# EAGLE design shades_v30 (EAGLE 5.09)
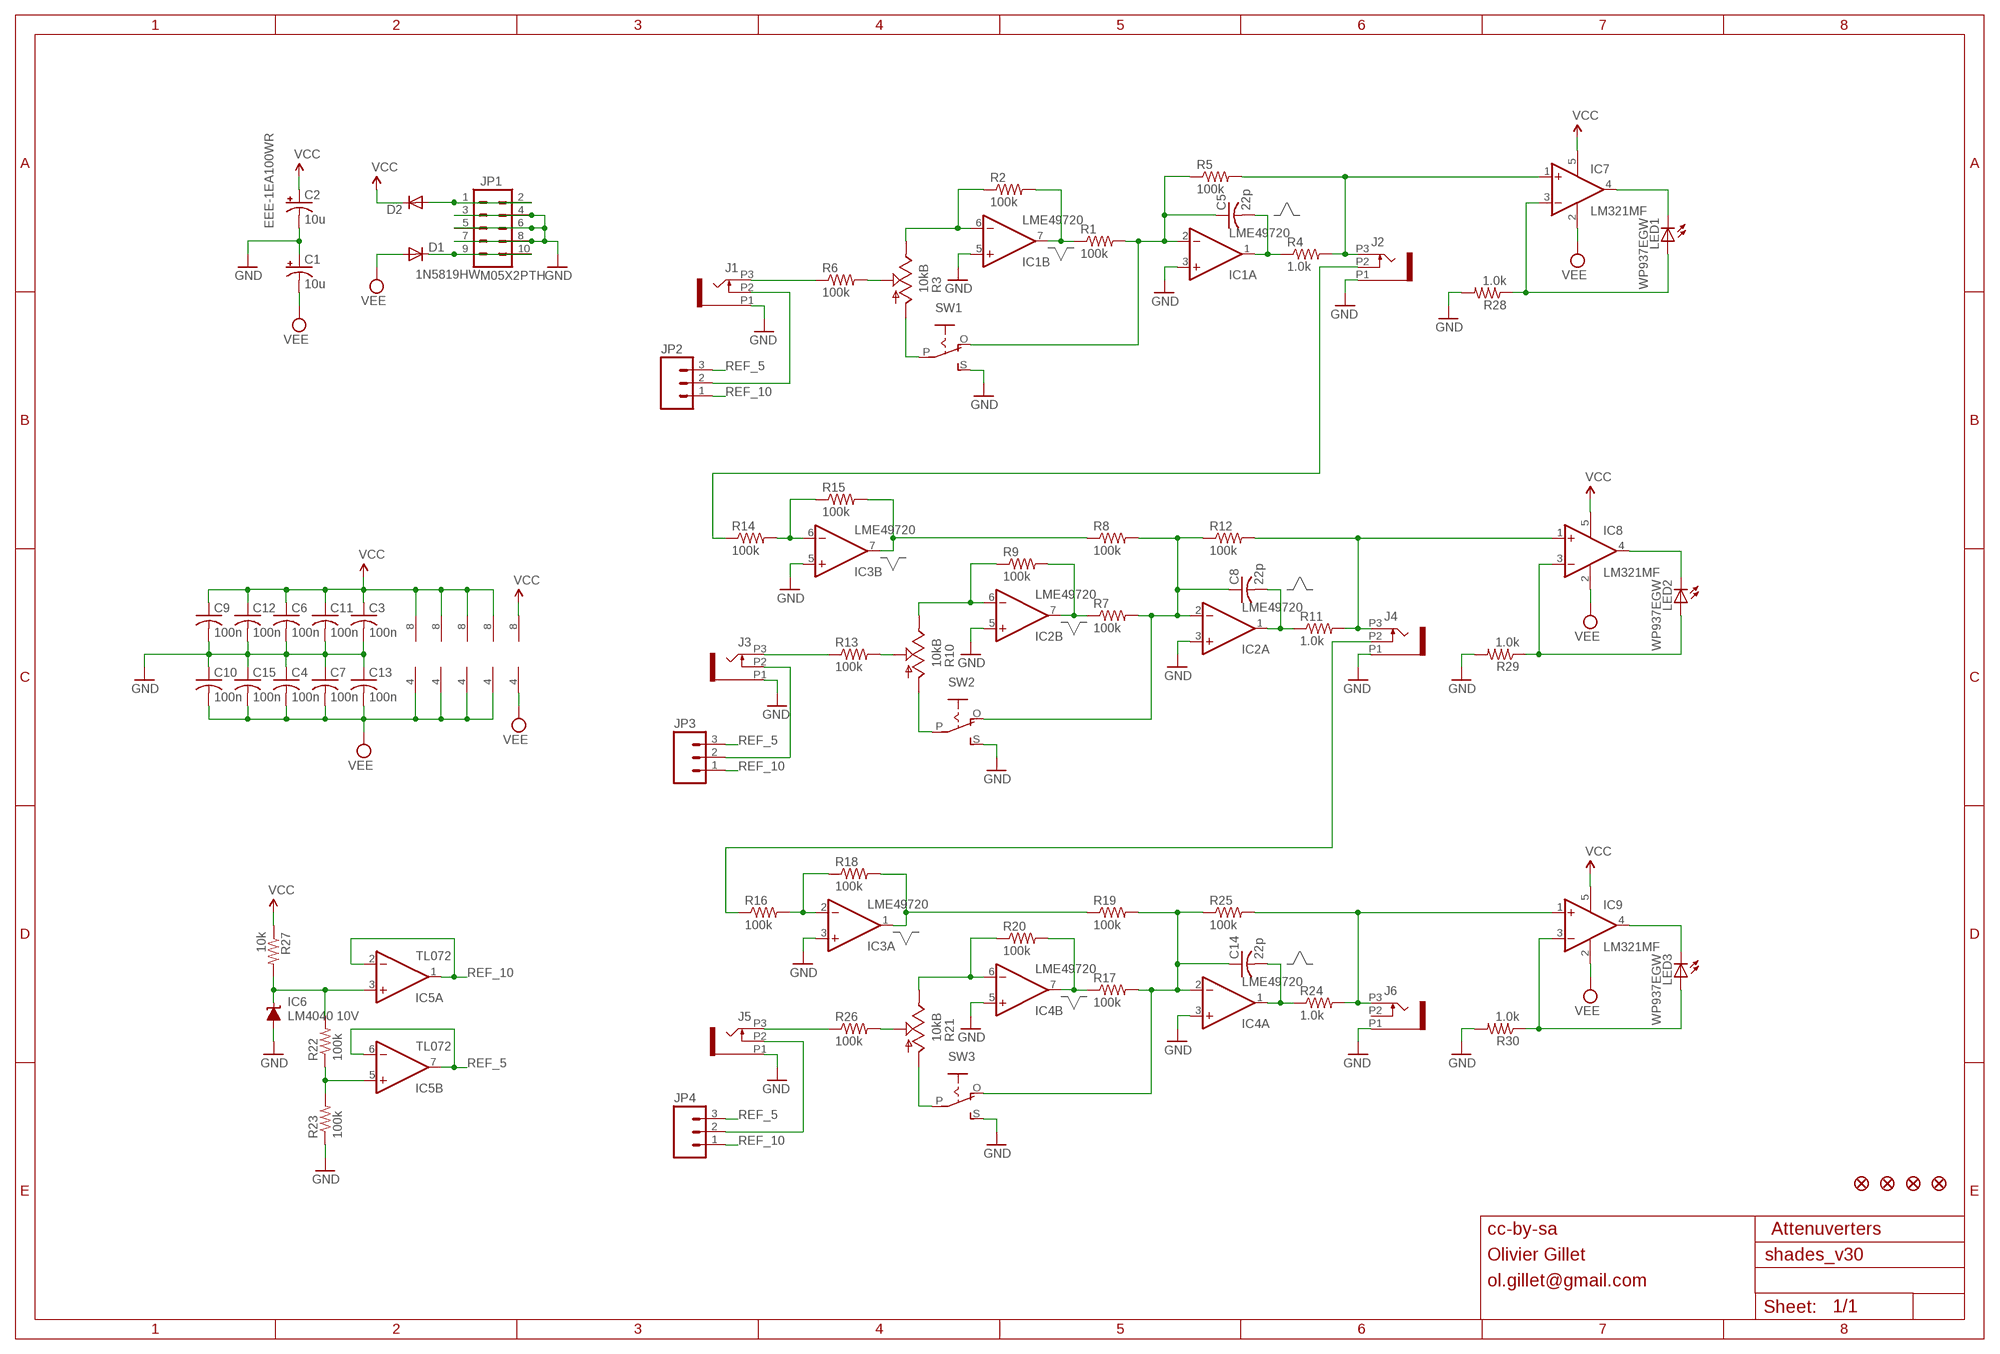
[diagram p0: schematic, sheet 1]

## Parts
C1  10u  CPOL-USB  [PANASONIC_B]
C2  10u  CPOL-USB  [PANASONIC_B]
C3  100n  C-USC0603  [C0603]
C4  100n  C-USC0603  [C0603]
C5  22p  C-USC0603  [C0603]
C6  100n  C-USC0603  [C0603]
C7  100n  C-USC0603  [C0603]
C8  22p  C-USC0603  [C0603]
C9  100n  C-USC0603  [C0603]
C10  100n  C-USC0603  [C0603]
C11  100n  C-USC0603  [C0603]
C12  100n  C-USC0603  [C0603]
C13  100n  C-USC0603  [C0603]
C14  22p  C-USC0603  [C0603]
C15  100n  C-USC0603  [C0603]
D1  1N5819HW  DIODE-SOD123  [SOD123]
D2  1N5819HW  DIODE-SOD123  [SOD123]
F1  FIDUCIAL1X2  [FIDUCIAL-1X2]
F2  FIDUCIAL1X2  [FIDUCIAL-1X2]
F3  FIDUCIAL1X2  [FIDUCIAL-1X2]
F4  FIDUCIAL1X2  [FIDUCIAL-1X2]
IC1  LME49720  TL072D  [SO08]
IC2  LME49720  TL072D  [SO08]
IC3  LME49720  TL072D  [SO08]
IC4  LME49720  TL072D  [SO08]
IC5  TL072  TL072D  [SO08]
IC6  LM4040 10V  LM4041C12DBZ  [DBZ_R-PDSO-G3]
IC7  LM321MF  [SOT23-5]
IC8  LM321MF  [SOT23-5]
IC9  LM321MF  [SOT23-5]
J1  PJ301_THONKICONN6  [WQP_PJ_301M6]
J2  PJ301_THONKICONN6  [WQP_PJ_301M6]
J3  PJ301_THONKICONN6  [WQP_PJ_301M6]
J4  PJ301_THONKICONN6  [WQP_PJ_301M6]
J5  PJ301_THONKICONN6  [WQP_PJ_301M6]
J6  PJ301_THONKICONN6  [WQP_PJ_301M6]
JP1  M05X2PTH  [AVR_ICSP]
JP2  M03PTH  [1X03]
JP3  M03PTH  [1X03]
JP4  M03PTH  [1X03]
LED1  WP937EGW  LED3MM  [LED3MM]
LED2  WP937EGW  LED3MM  [LED3MM]
LED3  WP937EGW  LED3MM  [LED3MM]
R1  100k  R-US_R0603  [R0603]
R2  100k  R-US_R0603  [R0603]
R3  10kB  POT_USVERTICAL_PS  [ALPS_POT_VERTICAL_PS]
R4  1.0k  R-US_R0603  [R0603]
R5  100k  R-US_R0603  [R0603]
R6  100k  R-US_R0603  [R0603]
R7  100k  R-US_R0603  [R0603]
R8  100k  R-US_R0603  [R0603]
R9  100k  R-US_R0603  [R0603]
R10  10kB  POT_USVERTICAL_PS  [ALPS_POT_VERTICAL_PS]
R11  1.0k  R-US_R0603  [R0603]
R12  100k  R-US_R0603  [R0603]
R13  100k  R-US_R0603  [R0603]
R14  100k  R-US_R0603  [R0603]
R15  100k  R-US_R0603  [R0603]
R16  100k  R-US_R0603  [R0603]
R17  100k  R-US_R0603  [R0603]
R18  100k  R-US_R0603  [R0603]
R19  100k  R-US_R0603  [R0603]
R20  100k  R-US_R0603  [R0603]
R21  10kB  POT_USVERTICAL_PS  [ALPS_POT_VERTICAL_PS]
R22  100k  R-US_R0603  [R0603]
R23  100k  R-US_R0603  [R0603]
R24  1.0k  R-US_R0603  [R0603]
R25  100k  R-US_R0603  [R0603]
R26  100k  R-US_R0603  [R0603]
R27  10k  R-US_R0603  [R0603]
R28  1.0k  R-US_R0603  [R0603]
R29  1.0k  R-US_R0603  [R0603]
R30  1.0k  R-US_R0603  [R0603]
SW1  S-ON-ONSMALL_SLIDE  [ES_100SP1T6B11M2QEH_SMALL]
SW2  S-ON-ONSMALL_SLIDE  [ES_100SP1T6B11M2QEH_SMALL]
SW3  S-ON-ONSMALL_SLIDE  [ES_100SP1T6B11M2QEH_SMALL]

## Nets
GND: C1.+ C2.- C3.2 C4.1 C6.2 C7.1 C9.2 C10.1 C11.2 C12.2 C13.1 C15.1 IC1.3(A:+IN) IC1.5(B:+IN) IC2.3(A:+IN) IC2.5(B:+IN) IC3.3(A:+IN) IC3.5(B:+IN) IC4.3(A:+IN) IC4.5(B:+IN) IC6.2(A) J1.P1 J2.P1 J3.P1 J4.P1 J5.P1 J6.P1 JP1.3 JP1.4 JP1.5 JP1.6 JP1.7 JP1.8 R23.1 R28.2 R29.2 R30.2 SW1.S SW2.S SW3.S
N$1: J1.P2 JP2.2
N$2: J3.P2 JP3.2
N$3: J5.P2 JP4.2
N$4: IC7.3(-IN) LED1.A R28.1
N$5: IC5.5(B:+IN) R22.1 R23.2
N$6: D2.A JP1.1 JP1.2
N$7: IC7.4(OUT) LED1.K(C)
N$9: J1.P3 R6.1
N$10: R3.P$2(S) R6.2
N$11: R3.P$3(A) SW1.P
N$12: C5.1 IC1.2(A:-IN) R1.2 R5.1 SW1.O
N$13: IC1.6(B:-IN) R2.1 R3.P$1(E)
N$14: IC1.7(B:OUT) R1.1 R2.2
N$15: C5.2 IC1.1(A:OUT) R4.1
N$16: J3.P3 R13.1
N$17: IC8.3(-IN) LED2.A R29.1
N$18: R10.P$2(S) R13.2
N$19: R10.P$3(A) SW2.P
N$20: D1.C JP1.9 JP1.10
N$22: IC2.6(B:-IN) R9.1 R10.P$1(E)
N$23: IC2.7(B:OUT) R7.1 R9.2
N$24: IC8.4(OUT) LED2.K(C)
N$25: C8.2 IC2.1(A:OUT) R11.1
N$26: J5.P3 R26.1
N$27: R21.P$2(S) R26.2
N$30: IC4.6(B:-IN) R20.1 R21.P$1(E)
N$31: IC4.7(B:OUT) R17.1 R20.2
N$33: C14.2 IC4.1(A:OUT) R24.1
N$34: IC9.3(-IN) LED3.A R30.1
N$35: IC9.4(OUT) LED3.K(C)
N$36: IC3.6(B:-IN) R14.2 R15.1
N$37: IC3.2(A:-IN) R16.2 R18.1
N$38: IC3.1(A:OUT) R18.2 R19.1
N$39: IC3.7(B:OUT) R8.1 R15.2
N$40: C14.1 IC4.2(A:-IN) R17.2 R19.2 R25.1 SW3.O
N$41: C8.1 IC2.2(A:-IN) R7.2 R8.2 R12.1 SW2.O
OUT_1: IC7.1(+IN) J2.P3 R4.2 R5.2
OUT_2: IC8.1(+IN) J4.P3 R11.2 R12.2
OUT_3: IC9.1(+IN) J6.P3 R24.2 R25.2
REF_5: IC5.6(B:-IN) IC5.7(B:OUT) JP2.3 JP3.3 JP4.3
REF_10: IC5.1(A:OUT) IC5.2(A:-IN) JP2.1 JP3.1 JP4.1
REF_10_UNBUF: IC5.3(A:+IN) IC6.1(C) R22.2 R27.2
SEND_1: J2.P2 R14.1
SEND_2: J4.P2 R16.1
SW3: R21.P$3(A) SW3.P
VCC: C2.+ C3.1 C6.1 C9.1 C11.1 C12.1 D2.C IC1.8(P:V+) IC2.8(P:V+) IC3.8(P:V+) IC4.8(P:V+) IC5.8(P:V+) IC7.5(V+) IC8.5(V+) IC9.5(V+) R27.1
VEE: C1.- C4.2 C7.2 C10.2 C13.2 C15.2 D1.A IC1.4(P:V-) IC2.4(P:V-) IC3.4(P:V-) IC4.4(P:V-) IC5.4(P:V-) IC7.2(V-) IC8.2(V-) IC9.2(V-)
Unconnected: J6.P2

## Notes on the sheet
- EEE-1EA100WR
- cc-by-sa | Attenuverters
- Olivier Gillet
- ol.gillet@gmail.com

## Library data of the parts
C1 C2 = rcl:CPOL-US: POLARIZED CAPACITOR, American symbol
C3-C15 = rcl:C-US: CAPACITOR, American symbol
D1 D2 = diode:DIODE-: DIODE
F1-F4 = SparkFun:FIDUCIAL: Fiducial Alignment Points
IC1-IC5 = gm-ics:TL072: OP AMP
IC6 = texas:LM4041: PRECISION MICROPOWER SHUNT VOLTAGE REFERENCE
IC7-IC9 = linear:LM321?*: Low Power Single Op Amp Source: http://cache.national.com/ds/LM/LM321.pdf
J1-J6 = og-pj301:PJ301_THONKICONN
JP1 = og-header:M05X2: Header 5x2 Standard 10-pin dual row 0.1" header. Commonly used with AVR-ISP. Use with Spark Fun Electronics SKU: PRT-00778
JP2-JP4 = SparkFun:M03: Header 3 Standard 3-pin 0.1" header. Use with straight break away headers (SKU : PRT-00116), right angle break away headers (PRT-00553), swiss pins (PRT-00743), machine pins (PRT-00117), and female headers (PRT-00115). Molex polarized connector foot print use with SKU : PRT-08232 with associated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
LED1-LED3 = led:LED: LED
R1 R2 R4-R9 R11-R20 R22-R26 R28-R30 = rcl:R-US_: RESISTOR, American symbol
R3 R10 R21 = pot-alps:POT_US
R27 = resistor:R-US_: RESISTOR, American symbol
SW1-SW3 = og-switch:S-ON-ON: On-on Switch

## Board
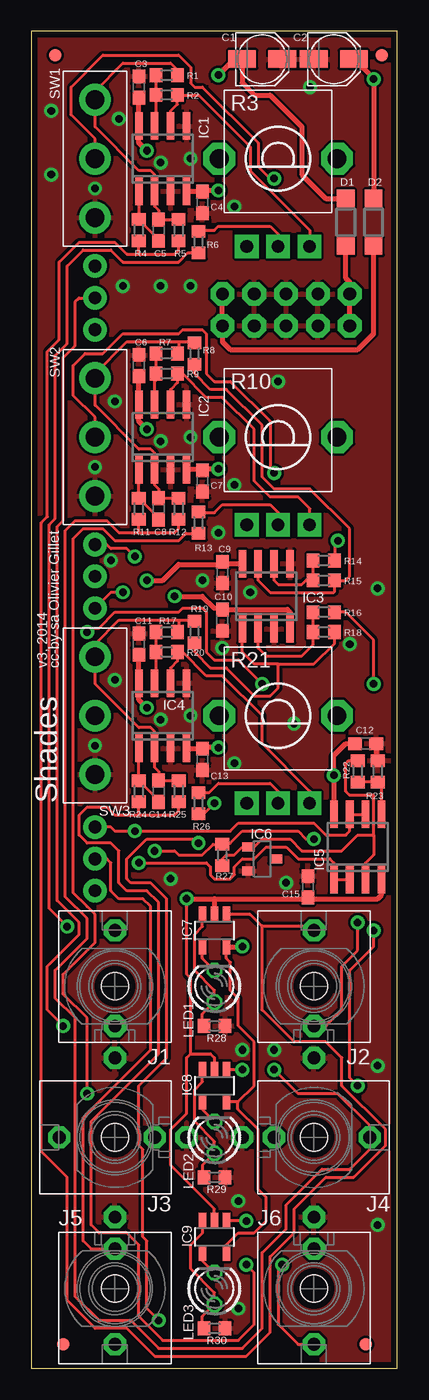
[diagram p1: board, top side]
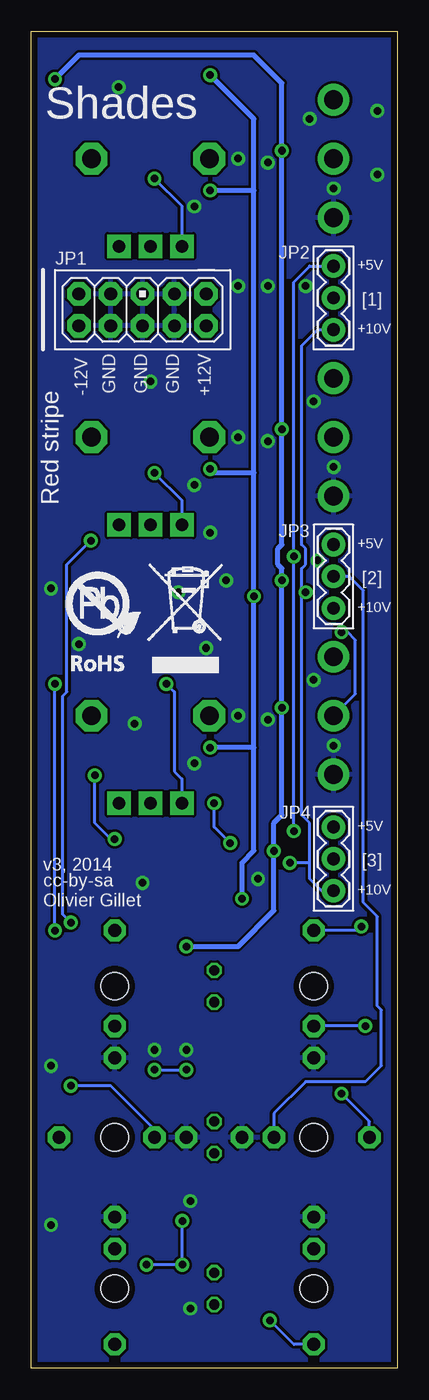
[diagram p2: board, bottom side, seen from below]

Size 29.19 x 106.68 mm. Coordinates in mm from the lower left corner, seen from the top.
Outline: 0,0 29.19,0 29.19,106.68 0,106.68 0,0
Copper layers (1*16): Top 0.035mm / dielectric 1.5mm / Bottom 0.035mm
Design rules "PCBCart-Standard": minimum track width 8mil, minimum drill 0.4mm, track to track 8mil, track to pad 8mil, pad to pad 8mil, via to via 8mil, smd to smd 8mil, copper to edge 20mil, drill to drill 8mil, minimum pad ring 8mil, minimum via ring 10mil, stop-mask expansion 3mil, vias tented up to drill 25mil, thermal gap 8mil

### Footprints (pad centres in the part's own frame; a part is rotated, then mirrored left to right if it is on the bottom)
PANASONIC_B = smd 2.2 x 1.4: + 1.6,0; - -1.6,0
C0603 = smd 1.1 x 1: 1 -0.85,0; 2 0.85,0
SOD123 = smd 1.4 x 1.4: A 1.9,0; C -1.9,0
FIDUCIAL-1X2 = smd 1 x 1: 1 0,0
SO08 = smd 0.6 x 2.2: 1 -1.905,-2.6; 2 -0.635,-2.6; 3 0.635,-2.6; 4 1.905,-2.6; 5 1.905,2.6; 6 0.635,2.6; 7 -0.635,2.6; 8 -1.905,2.6
DBZ_R-PDSO-G3 = smd 0.7 x 1: 1 -0.95,-1.1; 2 0.95,-1.1; 3 0,1.1
SOT23-5 = smd 0.6 x 1.2: 1 -0.95,-1.306; 2 0,-1.306; 3 0.95,-1.306; 4 0.95,1.306; 5 -0.95,1.306
WQP_PJ_301M6 = drill 1.016 pad 1.778 octagon: P1 0,-5.715; P2 0,-3.175; P3 0,4.445 | hole 2.2: 0,0
AVR_ICSP = drill 1.016 pad 1.88 octagon: 1 -1.27,5.08; 2 1.27,5.08; 3 -1.27,2.54; 4 1.27,2.54; 5 -1.27,0; 6 1.27,0; 7 -1.27,-2.54; 8 1.27,-2.54; 9 -1.27,-5.08; 10 1.27,-5.08
1X03 = drill 1.016 pad 1.88 round: 1 0,0; 2 2.54,0; 3 5.08,0
LED3MM = drill 0.813 octagon: A -1.27,0; K 1.27,0
R0603 = smd 1 x 1.1: 1 -0.85,0; 2 0.85,0
ALPS_POT_VERTICAL_PS = drill 1 pad 1.88 square: P$1 -2.5,7; P$2 0,7; P$3 2.5,7 | drill 1.5 pad 2.54 octagon: P$4 -4.7,0; P$5 4.7,0
ES_100SP1T6B11M2QEH_SMALL = drill 1.5 pad 2.54 round: O -4.699,0; P 0,0; S 4.699,0

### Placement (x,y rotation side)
C1  18.41,104.46 0 top
C2  24.13,104.46 0 top
C3  8.57,102.24 90 top
C4  13.65,93.03 90 top
C5  10.16,90.81 270 top
C6  8.57,80.01 90 top
C7  13.65,70.8 90 top
C8  10.16,68.58 270 top
C9  15.24,63.5 270 top
C10  15.24,59.69 90 top
C11  8.57,57.78 90 top
C12  26.67,49.85 0 top
C13  13.65,48.58 90 top
C14  10.16,46.04 270 top
C15  22.07,38.42 270 top
D1  25.08,91.44 90 top
D2  27.31,91.44 270 top
F1  1.91,104.78 90 top
F2  27.94,104.78 90 top
F3  2.54,1.91 90 top
F4  26.67,1.91 90 top
IC1  10.48,96.52 0 top
IC2  10.48,74.3 0 top
IC3  18.73,61.59 0 top
IC4  10.48,52.07 0 top
IC5  26.04,41.59 0 top
IC6  18.41,40.64 270 top
IC7  14.61,34.92 180 top
IC8  14.61,22.54 180 top
IC9  14.61,10.48 180 top
J1  6.67,30.48 0 top
J2  22.54,30.48 0 top
J3  6.67,18.41 90 top
J4  22.54,18.41 270 top
J5  6.67,6.35 180 top
J6  22.54,6.35 180 top
JP1  20.32,84.45 270 bottom
JP2  5.08,82.87 90 bottom
JP3  5.08,60.64 90 bottom
JP4  5.08,38.1 90 bottom
LED1  14.61,30.48 90 top
LED2  14.61,18.41 90 top
LED3  14.61,6.35 90 top
R1  10.79,103.19 0 top
R2  10.79,101.6 180 top
R3  19.68,96.52 180 top
R4  8.57,90.81 270 top
R5  11.75,90.81 270 top
R6  13.34,89.85 90 top
R7  10.79,80.96 0 top
R8  13.02,80.96 90 top
R9  10.79,79.38 180 top
R10  19.68,74.3 180 top
R11  8.57,68.58 270 top
R12  11.75,68.58 270 top
R13  13.33,67.47 90 top
R14  23.34,64.45 180 top
R15  23.34,62.87 0 top
R16  23.34,60.33 180 top
R17  10.79,58.74 0 top
R18  23.34,58.74 0 top
R19  13.02,58.74 90 top
R20  10.8,57.15 180 top
R21  19.68,52.07 180 top
R22  26.04,47.62 90 top
R23  27.62,47.62 270 top
R24  8.57,46.04 270 top
R25  11.75,46.04 270 top
R26  13.34,45.09 90 top
R27  15.24,40.96 270 top
R28  14.61,27.3 0 top
R29  14.61,15.24 0 top
R30  14.61,3.17 0 top
SW1  5.08,96.52 270 top
SW2  5.08,74.3 270 top
SW3  5.08,52.07 270 top
U$2  [ROHS]  27.3,54.93 0 bottom

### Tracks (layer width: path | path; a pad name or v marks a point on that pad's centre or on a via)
GND  (via drill 0.6)
  Top 0.254: 27.52,48.58 R23.1
  Top 0.406: C12.2 27.52,48.58
  other vias: 16.51,13.34 16.83,25.4 12.7,96.52 5.08,94.14 5.08,71.91 12.7,74.3 16.19,92.71 16.19,70.48 5.08,49.69 12.7,52.07 16.19,48.26 27.62,62.23 13.65,62.87 15.24,57.47 22.23,102.23 7.3,86.36 12.7,86.36 6.99,99.69 6.67,77.15 6.67,54.93 20.32,38.73 25.4,57.78 20.95,51.44 17.46,61.91 6.35,64.45 14.92,66.67 1.59,100.33 1.59,95.25 27.62,11.43 27.62,24.13 19.37,25.4 19.68,78.74 10.32,73.98 10.32,51.75 11.11,39.05 10.32,86.36 10.32,96.2 16.51,4.76
  pour Bottom: 0,106.68 0,0 29.21,0 29.21,106.68
  pour Top: 0,106.68 0,0 29.21,0 29.21,106.68
N$1  (via drill 0.6)
  Top 0.254: JP2.2 3.81,85.41 3.49,85.09 3.49,81.6 2.54,80.64 2.54,67.63 2.06,67.15 2.06,37.31 3.81,35.56 3.81,34.61 1.27,32.07 1.27,28.57 v2.54,27.3
  Bottom 0.254: v2.54,27.3 J1.P2
N$2
  Bottom 0.254: JP3.2 3.81,63.18 2.7,62.07 2.7,37.15 1.59,36.04 1.59,28.89 1.27,28.57 1.27,24.13 2.54,22.86 7.3,22.86 9.84,20.32 J3.P2
N$3
  Top 0.254: JP4.2 6.03,40.64 6.35,40.32 6.35,38.1 6.99,37.47 8.89,37.47 9.53,36.83 9.53,25.4 4.13,20 4.13,10.16 4.76,9.53 J5.P2
N$4
  Top 0.254: R28.1 13.65,27.41 13.65,28.26 LED1.A 14.61,30.16 13.02,31.75 13.02,34.61 13.65,35.24 IC7.3
N$5
  Top 0.254: R22.1 R23.2 27.62,46.67 27.94,46.35 IC5.5
N$6
  Top 0.406: D2.A | D2.A 27.3,82.55 26.04,81.28 15.88,81.28 15.24,81.92 JP1.2 JP1.1
N$7
  Top 0.254: IC7.4 13.65,32.7 LED1.K
N$9  (via drill 0.6)
  Top 0.254: v2.86,35.24 1.43,36.67 1.43,67.31 1.91,67.79 1.91,80.8 2.86,81.76 2.86,87.95 4.13,89.22 6.35,89.22 7.3,88.27 11.75,88.27 12.48,89 R6.1
  Bottom 0.254: v2.86,35.24 2.9,35.28 3.25,34.92 J1.P3
N$10
  Top 0.254: R6.2 13.44,90.81 14.61,90.81 14.92,91.12 19.05,91.12 19.68,90.49 R3.P$2
N$11  (via drill 0.6)
  Top 0.254: v19.37,94.93 19.05,94.93 18.1,95.89 18.1,97.79 13.65,102.23 13.02,102.23 12.7,102.55 12.7,103.82 11.75,104.78 5.71,104.78 3.17,102.23 3.17,100.01 5.08,98.11 SW1.P
  Bottom 0.254: v19.37,94.93 17.18,92.75 R3.P$3
N$12
  Top 0.254: R5.1 C5.1 10.16,92.39 9.84,92.71 IC1.2 9.84,95.25 9.53,95.57 8.57,95.57 5.08,99.06 SW1.O 5.08,101.92 7.3,104.14 11.11,104.14 11.64,103.61 R1.2
N$13
  Top 0.254: IC1.6 11.11,100.33 11.64,100.86 R2.1 13.34,101.6 17.46,97.47 17.46,95.57 22.23,90.81 22.23,89.56 R3.P$1
N$14
  Top 0.254: IC1.7 9.95,99.22 R2.2 | R2.2 | R2.2 R1.1
N$15
  Top 0.254: IC1.1 R4.1 10.16,90.07 C5.2
N$16  (via drill 0.6)
  Top 0.254: 4.45,36.83 3.33,37.94 3.33,66.2 4.13,66.99 5.71,66.99 6.67,66.04 11.75,66.04 12.33,66.62 R13.1 | 4.45,36.83 | 4.45,36.83 5.08,36.2 5.08,33.97 2.54,31.43 2.54,29.84 4.45,27.94 v4.45,21.91
  Bottom 0.254: v4.45,21.91 2.22,19.68 J3.P3
N$17
  Top 0.254: R29.1 13.65,15.34 13.65,16.19 LED2.A 14.61,18.1 13.02,19.68 13.02,22.23 13.65,22.86 IC8.3
N$18
  Top 0.254: R13.2 13.39,68.26 14.61,68.26 15.24,68.9 19.05,68.9 19.68,68.26 R10.P$2
N$19  (via drill 0.6)
  Top 0.254: v19.37,71.44 19.05,71.75 19.05,75.56 15.88,78.74 14.61,78.74 13.97,79.38 13.97,82.55 13.65,82.87 12.06,82.87 11.75,82.55 7.3,82.55 5.71,80.96 4.29,80.96 3.33,80.01 3.33,77.63 5.08,75.88 SW2.P
  Bottom 0.254: v19.37,71.44 17.18,69.25 R10.P$3
N$20
  Top 0.406: JP1.10 JP1.9 25.4,86.68 25.08,87 D1.C
N$22
  Top 0.254: R10.P$1 22.23,67.33 22.23,68.58 21.27,69.53 19.05,69.53 17.78,70.8 17.78,74.93 15.24,77.47 13.97,77.47 12.06,79.38 R9.1 11.64,78.64 11.11,78.11 IC2.6
N$23
  Top 0.254: IC2.7 9.84,78.74 9.95,78.84 R9.2 R7.1
N$24
  Top 0.254: IC8.4 13.65,20.64 LED2.K
N$25
  Top 0.254: IC2.1 R11.1 10.16,67.84 C8.2
N$26  (via drill 0.6)
  Top 0.254: v13.34,41.91 13.02,42.23 9.21,42.23 7.62,40.64 7.62,39.05 7.94,38.73 9.53,38.73 10.79,37.47 10.79,24.77 8.57,22.54 8.57,17.78 8.89,17.46 8.89,10.48 9.21,10.16 9.21,4.76 v10.16,3.81 | v14.61,45.09 13.76,44.23 R26.1
  Bottom 0.254: v13.34,41.91 14.61,43.18 v14.61,45.09 | v10.16,3.81 8.26,1.91 J5.P3
N$27
  Top 0.254: R21.P$2 19.68,46.04 19.05,46.67 14.92,46.67 14.19,45.94 R26.2
N$30
  Top 0.254: IC4.6 | IC4.6 11.11,55.88 11.64,56.41 R20.1 12.06,57.15 13.97,55.24 15.24,55.24 18.41,52.07 18.41,49.85 22.23,46.04 22.23,45.11 R21.P$1
N$31
  Top 0.254: IC4.7 9.95,54.77 R20.2 | R20.2 | R20.2 R17.1
N$33
  Top 0.254: IC4.1 R24.1 10.16,45.3 C14.2
N$34
  Top 0.254: R30.1 13.65,3.28 13.65,4.13 LED3.A 14.61,6.03 12.7,7.94 12.7,9.84 13.65,10.8 IC9.3
N$35
  Top 0.254: IC9.4 13.65,8.57 LED3.K
N$36
  Top 0.254: IC3.6 19.37,62.87 19.68,62.55 21.59,62.55 21.91,62.87 R15.1 R14.2
N$37
  Top 0.254: IC3.2 18.1,57.47 18.73,56.83 21.59,56.83 22.49,57.73 R18.1 R16.2
N$38
  Top 0.254: R19.1 13.02,57.15 14.29,55.88 15.56,55.88 17.78,53.66 19.05,53.66 19.68,54.29 19.68,56.2 | IC3.1 16.83,57.15 17.78,56.2 19.68,56.2 | 19.68,56.2 22.54,56.2 24.19,57.84 R18.2
N$39
  Top 0.254: R8.1 13.02,79.38 14.29,78.11 15.56,78.11 18.41,75.25 18.41,71.12 19.37,70.17 22.23,70.17 25.4,66.99 25.4,63.18 25.08,62.87 R15.2 24.19,61.97 24.13,61.91 19.05,61.91 18.1,62.87 IC3.7
N$40
  Top 0.254: C14.1 | C14.1 10.16,47.62 9.84,47.94 IC4.2 9.84,50.8 | C14.1 R25.1 | R19.2 12.91,59.69 11.75,59.69 | 11.75,59.69 6.99,59.69 5.08,57.78 SW3.O 5.08,54.61 8.57,51.12 9.53,51.12 9.84,50.8 | R17.2 11.75,58.84 11.75,59.69 | 9.84,50.8
N$41
  Top 0.254: R12.1 C8.1 10.16,70.17 9.84,70.48 IC2.2 9.84,73.03 9.53,73.34 8.57,73.34 5.08,76.83 SW2.O 5.08,79.38 7.62,81.92 11.75,81.92 | R7.2 11.75,81.06 11.75,81.92 | R8.2 12.91,81.92 11.75,81.92
OUT_1
  Top 0.254: IC7.1 15.59,36.2 17.46,36.2 18.38,35.28 18.41,35.28 | R5.2 11.75,89.22 11.43,88.9 8.57,88.9 | 8.57,88.9 7.62,88.9 6.67,89.85 3.81,89.85 2.22,88.27 2.22,82.07 1.27,81.12 1.27,67.94 0.79,67.47 0.79,17.3 2.86,15.24 2.86,5.4 5.08,3.17 7.62,3.17 9.84,0.95 17.14,0.95 19.05,2.86 19.05,8.89 20.95,10.79 20.95,12.7 23.5,15.24 25.72,15.24 28.26,17.78 28.26,19.05 24.77,22.54 24.77,24.77 23.5,26.04 20.95,26.04 18.41,28.57 18.41,35.28 | 8.57,88.9 R4.2 | J2.P3 22.19,35.28 18.41,35.28
OUT_2  (via drill 0.6)
  Top 0.254: IC8.1 15.59,23.81 v16.83,23.81 | R12.2 11.75,66.99 11.43,66.67 8.57,66.67 | 8.57,66.67 6.99,66.67 6.03,67.63 3.49,67.63 2.7,66.83 2.7,37.62 4.45,35.88 4.45,34.29 1.91,31.75 1.91,29.53 3.49,27.94 3.49,5.71 5.4,3.81 7.94,3.81 10.16,1.59 16.83,1.59 18.41,3.17 18.41,9.21 20.32,11.11 20.32,13.02 23.18,15.88 25.4,15.88 26.99,17.46 J4.P3 26.99,19.37 24.45,21.91 21.27,21.91 v19.37,23.81 | 8.57,66.67 R11.2
  Bottom 0.254: v19.37,23.81 v16.83,23.81
OUT_3  (via drill 0.6)
  Top 0.254: IC9.1 15.59,11.75 v17.14,11.75 | R25.2 11.75,44.45 11.43,44.13 8.57,44.13 | 8.57,44.13 6.67,44.13 6.03,44.77 4.45,44.77 3.81,44.13 3.81,42.55 4.45,41.91 6.35,41.91 6.99,41.27 6.99,38.73 7.62,38.1 9.21,38.1 10.16,37.15 10.16,25.08 4.76,19.68 4.76,11.43 5.4,10.79 7.62,10.79 8.57,9.84 8.57,4.13 10.48,2.22 16.51,2.22 17.78,3.49 17.78,7.62 v17.14,8.26 | R24.2 8.57,44.13 | v20,8.26 19.68,7.94 19.68,3.49 21.27,1.91 J6.P3
  Bottom 0.254: v17.14,11.75 v17.14,8.26 v20,8.26
REF_5  (via drill 0.6)
  Top 0.254: JP3.3 6.03,65.72 6.35,65.41 7.62,65.41 v8.26,64.77 | JP4.3 6.35,43.18 6.67,42.86 v8.26,42.86 15.88,42.86 16.51,43.5 22.54,43.5 23.5,42.55 25.08,42.55 25.4,42.86 IC5.7 IC5.6
  Bottom 0.254: JP2.3 6.99,87.95 8.26,86.68 v8.26,64.77 v8.26,42.86
REF_10  (via drill 0.6)
  Top 0.254: IC5.2 IC5.1 24.13,40.32 23.81,40.64 21.27,40.64 20.32,41.59 18.73,41.59 17.78,40.64 16.83,40.64 16.19,40.01 16.19,39.37 15.88,39.05 14.61,39.05 14.29,39.37 14.29,40.01 13.97,40.32 v8.57,40.32 | JP3.1 6.35,61.91 v7.3,61.91
  Bottom 0.254: JP2.1 6.35,82.87 7.62,81.6 7.62,65.72 7.3,65.41 7.3,64.14 7.62,63.82 7.62,61.91 | 6.99,40.32 6.99,43.5 7.62,44.13 7.62,61.91 | 6.99,40.32 v8.57,40.32 | 6.99,40.32 6.99,39.05 6.03,38.1 JP4.1 | 7.62,61.91 v7.3,61.91
REF_10_UNBUF
  Top 0.254: IC5.3 26.67,40.32 27.3,40.96 27.3,42.55 | 27.3,42.55 27.3,45.72 25.4,45.72 25.08,46.04 25.08,48.26 25.3,48.48 R22.2 | 27.3,42.55 26.04,42.55 24.77,41.27 21.59,41.27 20.64,42.23 18.41,42.23 17.78,41.59 IC6.1 16.82,41.59 16.19,40.96 15.56,40.96 15.24,40.64 R27.2
SEND_1  (via drill 0.6)
  Top 0.254: 24.13,64.51 R14.1 24.19,65.78 v24.45,66.04 | v26.04,35.56 26.04,33.34 24.77,32.07 24.77,28.57 23.5,27.3 J2.P2
  Bottom 0.254: v24.45,66.04 26.35,64.14 26.35,53.98 26.67,53.66 26.67,36.2 v26.04,35.56
SEND_2  (via drill 0.6)
  Top 0.254: v27.3,34.92 27.3,33.66 25.4,31.75 25.4,23.18 v26.04,22.54 | R16.1 25.08,60.33 27.3,58.1 v27.3,54.61
  Bottom 0.254: v27.3,34.92 v27.3,54.61 | v26.04,22.54 22.86,22.54 19.37,19.05 J4.P2
SW3  (via drill 0.6)
  Top 0.254: v4.45,58.74 4.76,59.05 5.4,59.05 6.67,60.33 11.75,60.33 12.06,60.64 13.65,60.64 13.97,60.33 13.97,57.15 14.61,56.52 16.51,56.52 v18.41,54.61
  Bottom 0.254: v4.45,58.74 3.97,58.74 3.33,58.1 3.33,53.82 SW3.P | R21.P$3 17.18,47.03 17.78,47.62 17.78,53.98 v18.41,54.61
VCC  (via drill 0.6)
  Top 0.254: IC7.5 15.56,32.7 15.88,32.38 15.88,30.16 16.51,29.53 16.51,27.3 17.78,26.04 17.78,22.54 16.47,21.24 | 16.47,21.24 IC8.5 | IC9.5 15.59,9.21 15.56,9.24 15.56,9.84 16.51,10.79 17.78,10.79 18.73,11.75 18.73,13.65 18.1,14.29 18.1,19.05 16.47,20.67 16.47,21.24 | 15.14,64.45 C9.1 | v22.54,42.23 21.91,42.23 21.27,42.86 16.83,42.86 15.88,41.91 15.34,41.91 R27.1 14.5,41.81 13.65,40.96 11.75,40.96 11.43,41.27 v9.84,41.27
  Top 0.406: D2.C | C6.1 IC2.8 8.57,75.56 v9.21,74.93 | v9.21,97.16 8.57,97.79 IC1.8 C3.1 | C11.1 IC4.8 8.57,53.34 v9.21,52.7 | C9.1 15.39,64.19 IC3.8 | 15.14,64.45 14.82,64.14 11.75,64.14 10.48,62.87 v9.21,62.87 | IC5.8 v24.13,47.31 24.13,48.9 25.08,49.85 C12.1 | v16.83,33.66 16.79,33.62 IC7.5 | D2.C v27.3,102.87 27.3,102.88 C2.+
  Bottom 0.254: v22.54,42.23 22.86,42.23 24.13,43.5 v24.13,47.31
  Bottom 0.406: v27.3,102.87 25.4,104.78 11.43,104.78 9.21,102.55 v9.21,97.16 v9.21,74.93 9.21,65.72 9.53,65.41 9.53,64.14 9.21,63.82 v9.21,62.87 v9.21,52.7 9.21,44.13 9.84,43.5 v9.84,41.27 9.84,36.51 12.7,33.66 v16.83,33.66
VEE  (via drill 0.6)
  Top 0.254: IC9.2 14.61,12.7 11.11,16.19 11.11,19.05 12.38,20.32 12.38,24.77 12.7,25.08 | 12.7,25.08 14.29,25.08 14.61,24.77 IC8.2 | v12.38,37.47 12.38,31.43 12.7,31.11 12.7,25.08 | 15.14,60.64 C10.2
  Top 0.406: 25.08,93.66 D1.A 23.5,93.34 21.59,95.25 21.59,99.06 19.05,101.6 17.78,101.6 16.82,102.56 C1.- 16.19,104.46 v14.92,103.19 | IC1.4 12.43,93.88 C4.2 13.76,93.98 v14.92,93.98 | v14.92,71.75 13.76,71.75 C7.2 13.61,71.69 IC2.4 | 12.34,49.43 IC4.4 12.43,49.43 C13.2 13.76,49.53 v14.92,49.53 | 15.14,60.64 14.61,60.64 13.65,61.59 v11.43,61.59 | IC3.4 20.64,60.33 20.42,60.54 C10.2 | IC5.4 27.94,37.78 27.62,37.47 22.23,37.47 22.12,37.57 C15.2 21.96,37.47 14.61,37.47 | v12.38,37.47 14.61,37.47 | 14.61,37.47 IC7.2
  Bottom 0.406: v14.92,93.98 11.43,93.98 | v14.92,71.75 14.61,71.44 11.43,71.44 | 11.43,71.44 11.43,93.98 | 11.43,49.53 v11.43,61.59 11.43,71.44 | 11.43,49.53 v14.92,49.53 | v14.92,103.19 11.43,99.69 11.43,93.98 | v12.38,37.47 12.38,40.32 11.43,41.27 11.43,49.53

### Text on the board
bPlace: +5V | [1] | +10V | Red stripe | +5V | [2] | +10V | +5V | [3] | +10V
tNames: v3, 2014 | cc-by-sa Olivier Gillet | Shades
bNames: Shades | +12V | GND | GND | GND | -12V | v3, 2014 | cc-by-sa | Olivier Gillet
Drill_legend: Drill legend | Date: 03/11/14 17:47 | 2.2000 mm / 86.614 mil | 1.5000 mm / 59.055 mil | 1.0160 mm / 40.000 mil | 1.0000 mm / 39.370 mil | 0.8128 mm / 32.000 mil | 0.6000 mm / 23.622 mil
